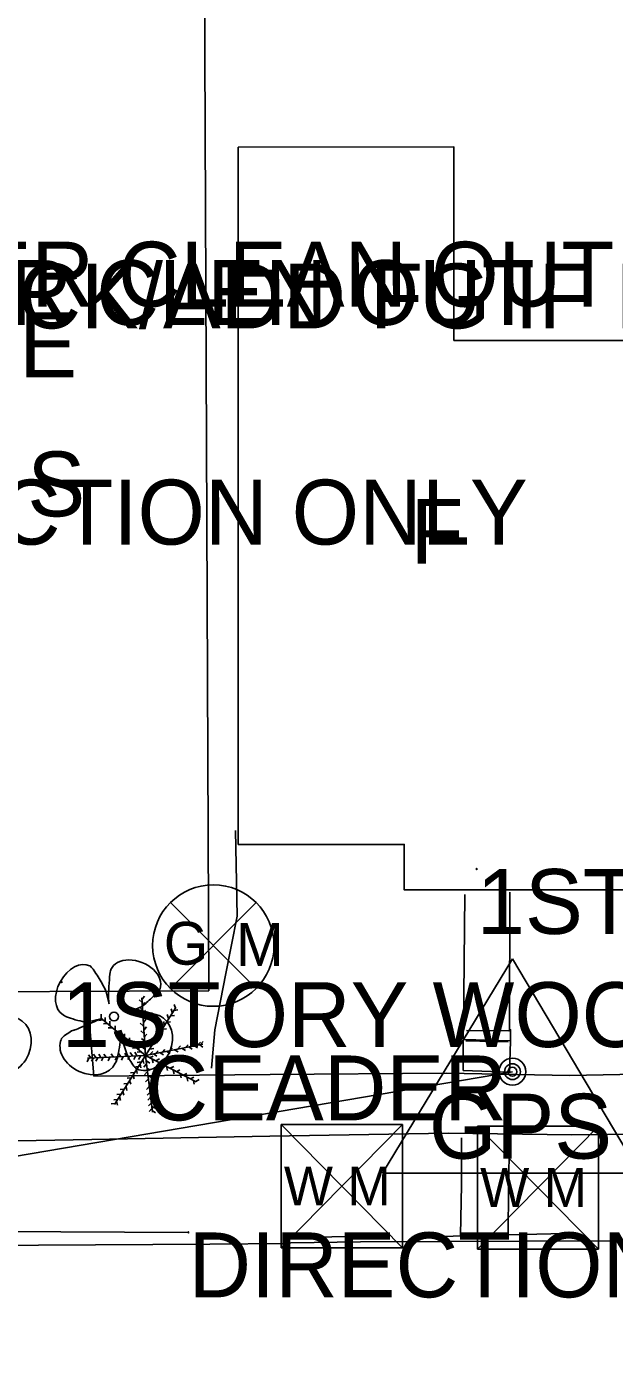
# Model space of a CAD drawing. Extents: x 1304270 to 1306561, y 1876019 to 1876752.
# Drawn here: x 1306274.6 to 1306320, y 1876424.3 to 1876526.4 of the extents above; entities that cross this region are included whole.
import ezdxf

# ---------------------------------------------------------------- set-up
doc = ezdxf.new("R2010")
doc.units = 0
for name, color, linetype in [('Default', 7, 'Continuous'), ('S_BUILDING', 7, 'Continuous'), ('S_BUILDING_ANNOT', 7, 'Continuous'), ('S_CURB', 7, 'Continuous'), ('S_DITCHLINE', 7, 'Continuous'), ('S_EDGE_CONCRETE', 7, 'Continuous'), ('S_EDGE_PAVEMENT', 7, 'Continuous'), ('S_GAS_UTILITIES', 7, 'Continuous'), ('S_MISC_STRUCTURES_ANNOT', 7, 'Continuous'), ('S_MSC_PT_SYM', 7, 'Continuous'), ('S_PRIMARY_CTL', 7, 'Continuous'), ('S_SANITARY_SEWER_ANNOT', 7, 'Continuous'), ('S_SIDEWALK', 7, 'Continuous'), ('S_STORM_SEWER', 7, 'Continuous'), ('S_STORM_SEWER_ANNOT', 7, 'Continuous'), ('S_STR_PT_SYM', 7, 'Continuous'), ('S_SURVEY_TEXT_ANNOT', 7, 'Continuous'), ('S_TREE', 7, 'Continuous'), ('S_TREE_ANNOT', 7, 'Continuous'), ('S_UTL_PT_SYM', 7, 'Continuous'), ('S_WATER_UTILITIES', 7, 'Continuous')]:
    doc.layers.add(name, color=color, linetype=linetype)

msp = doc.modelspace()

# ---------------------------------------------------------------- linework, layer by layer
at = {"layer": 'Default'}
msp.add_line((1305993.25, 1876391.55), (1306312.09, 1876445.88), dxfattribs=at)
at = {"layer": 'S_BUILDING'}
for points in [[(1306264.09, 1876452.02), (1306263.78, 1876530.37), (1306288.35, 1876530.47), (1306288.67, 1876452.12)], [(1306290.94, 1876517.15), (1306290.95, 1876463.4), (1306303.75, 1876463.4), (1306303.75, 1876459.89), (1306322.39, 1876459.89), (1306322.38, 1876502.24), (1306307.58, 1876502.24), (1306307.58, 1876517.16)]]:
    msp.add_lwpolyline(points, close=True, dxfattribs=at)
at = {"layer": 'S_CURB'}
for points in [[(1306295.32, 1876433.09), (1306299.61, 1876433.17)], [(1306306.43, 1876433.17), (1306316.12, 1876433.41)]]:
    msp.add_lwpolyline(points, dxfattribs=at)
at = {"layer": 'S_DITCHLINE'}
msp.add_lwpolyline([(1306290.74, 1876464.47), (1306290.85, 1876457.86), (1306289.99, 1876453.46), (1306289.14, 1876449.11), (1306288.88, 1876446.14)], dxfattribs=at)
at = {"layer": 'S_EDGE_CONCRETE'}
for points in [[(1306308.3, 1876445.97), (1306308.3, 1876448.25), (1306308.29, 1876448.38), (1306308.29, 1876449.07), (1306308.32, 1876449.22), (1306308.43, 1876459.54)], [(1306311.89, 1876459.71), (1306311.85, 1876449.16), (1306311.88, 1876449.02), (1306311.94, 1876449.12), (1306311.95, 1876448.96), (1306311.93, 1876448.26), (1306311.95, 1876448.23), (1306311.86, 1876445.84), (1306308.3, 1876445.97)], [(1306308.37, 1876448.37), (1306311.95, 1876448.26)], [(1306308.49, 1876448.27), (1306311.75, 1876448.17)], [(1306308.55, 1876449.06), (1306311.81, 1876449.03)]]:
    msp.add_lwpolyline(points, dxfattribs=at)
at = {"layer": 'S_EDGE_PAVEMENT'}
msp.add_lwpolyline([(1306113.12, 1876430.25), (1306126.16, 1876430.64), (1306148.96, 1876430.86), (1306171.76, 1876431.08), (1306196.43, 1876430.92), (1306201.22, 1876431.25), (1306201.59, 1876430.5), (1306204.64, 1876430.62), (1306209.26, 1876430.77), (1306212.62, 1876431.11), (1306218.85, 1876431.26), (1306235.37, 1876431.61), (1306256.72, 1876432.09), (1306262.37, 1876432.42), (1306275.55, 1876432.51), (1306288.74, 1876432.59), (1306294.65, 1876432.63), (1306294.99, 1876432.68), (1306300.36, 1876432.78), (1306312.86, 1876432.81), (1306325.37, 1876432.84), (1306326.28, 1876432.72), (1306334.35, 1876433.02), (1306341.35, 1876433.31)], dxfattribs=at)
at = {"layer": 'S_GAS_UTILITIES'}
for p, q in [((1306285.71, 1876452.29), (1306292.33, 1876458.91)), ((1306285.71, 1876458.91), (1306292.33, 1876452.29))]:
    msp.add_line(p, q, dxfattribs=at)
msp.add_circle((1306289.02, 1876455.6), 4.68, dxfattribs=at)
at = {"layer": 'S_MSC_PT_SYM'}
msp.add_lwpolyline([(1306277.32, 1876452.78), (1306277.32, 1876452.83), (1306277.32, 1876452.78), (1306277.28, 1876452.78), (1306277.32, 1876452.78), (1306277.32, 1876452.73), (1306277.32, 1876452.78), (1306277.38, 1876452.78)], dxfattribs=at)
at = {"layer": 'S_PRIMARY_CTL'}
for p, q in [((1306312.09, 1876454.58), (1306302.06, 1876438.07)), ((1306312.09, 1876454.58), (1306321.91, 1876438.07)), ((1306302.06, 1876438.07), (1306321.91, 1876438.07))]:
    msp.add_line(p, q, dxfattribs=at)
for radius in [1.04, 0.609, 0.344]:
    msp.add_circle((1306312.09, 1876445.88), radius, dxfattribs=at)
at = {"layer": 'S_SIDEWALK'}
for points in [[(1306279.53, 1876452.26), (1306279.47, 1876449.6), (1306279.8, 1876445.53)], [(1306279.8, 1876445.53), (1306293.4, 1876445.66), (1306307, 1876445.78)], [(1306307, 1876445.78), (1306316.52, 1876445.6), (1306328.09, 1876445.83), (1306340.2, 1876445.76), (1306355.77, 1876446.1)], [(1306258.08, 1876440.25), (1306262.7, 1876440.41), (1306268.2, 1876440.45), (1306279.65, 1876440.65), (1306293.39, 1876440.9), (1306307.14, 1876441.15), (1306316.67, 1876441.01), (1306327.71, 1876441.13), (1306341.95, 1876441.2), (1306356.19, 1876441.27)], [(1306308.16, 1876440.79), (1306308.15, 1876437.15), (1306308.08, 1876433.28)], [(1306311.77, 1876433.4), (1306311.79, 1876436.76), (1306311.87, 1876440.75)]]:
    msp.add_lwpolyline(points, dxfattribs=at)
at = {"layer": 'S_STORM_SEWER'}
msp.add_line((1306287.1, 1876433.49), (1306231.2, 1876433.73), dxfattribs=at)
at = {"layer": 'S_STR_PT_SYM'}
msp.add_lwpolyline([(1306309.34, 1876461.5), (1306309.34, 1876461.55), (1306309.34, 1876461.5), (1306309.29, 1876461.5), (1306309.34, 1876461.5), (1306309.34, 1876461.45), (1306309.34, 1876461.5), (1306309.39, 1876461.5)], dxfattribs=at)
at = {"layer": 'S_TREE'}
for p, q in [((1306280.99, 1876451.11), (1306280.75, 1876452.01)), ((1306283.53, 1876451.21), (1306283.31, 1876451.41)), ((1306283.79, 1876447.13), (1306283.52, 1876451.57)), ((1306283.53, 1876451.46), (1306283.72, 1876451.69)), ((1306283.56, 1876450.98), (1306283.74, 1876451.22)), ((1306280.36, 1876450.02), (1306280.36, 1876450.32)), ((1306282.94, 1876450.65), (1306283.32, 1876450.82)), ((1306283.56, 1876450.65), (1306283.34, 1876450.85)), ((1306283.59, 1876450.07), (1306283.37, 1876450.27)), ((1306283.59, 1876450.38), (1306283.78, 1876450.62)), ((1306283.79, 1876447.13), (1306286.13, 1876450.82)), ((1306285.56, 1876449.99), (1306285.47, 1876450.28)), ((1306285.75, 1876450.18), (1306286.04, 1876450.22)), ((1306285.86, 1876450.44), (1306285.77, 1876450.73)), ((1306285.99, 1876450.6), (1306286.29, 1876450.65)), ((1306286.1, 1876450.78), (1306286.01, 1876451.07)), ((1306280.34, 1876449.95), (1306279.37, 1876449.73)), ((1306280.5, 1876449.87), (1306280.2, 1876449.83)), ((1306283.79, 1876447.13), (1306280.32, 1876450.04)), ((1306280.85, 1876449.6), (1306280.55, 1876449.57)), ((1306280.68, 1876449.76), (1306280.68, 1876450.06)), ((1306281.21, 1876449.27), (1306280.91, 1876449.25)), ((1306281.03, 1876449.47), (1306281.03, 1876449.77)), ((1306281.44, 1876449.11), (1306281.44, 1876449.41)), ((1306283.62, 1876449.42), (1306283.39, 1876449.62)), ((1306283.63, 1876449.67), (1306283.82, 1876449.91)), ((1306283.69, 1876449.1), (1306283.88, 1876449.34)), ((1306284.89, 1876448.91), (1306284.8, 1876449.19)), ((1306285.1, 1876449.15), (1306285.4, 1876449.19)), ((1306285.26, 1876449.47), (1306285.17, 1876449.76)), ((1306285.42, 1876449.69), (1306285.72, 1876449.73)), ((1306281.67, 1876448.9), (1306281.37, 1876448.88)), ((1306282.03, 1876448.57), (1306281.73, 1876448.55)), ((1306281.86, 1876448.78), (1306281.86, 1876449.08)), ((1306281.88, 1876449.02), (1306281.96, 1876448.58)), ((1306282.37, 1876448.31), (1306282.07, 1876448.28)), ((1306282.18, 1876448.5), (1306282.18, 1876448.8)), ((1306282.55, 1876448.2), (1306282.55, 1876448.5)), ((1306282.91, 1876447.89), (1306282.91, 1876448.19)), ((1306283.66, 1876448.82), (1306283.43, 1876449.02)), ((1306283.7, 1876448.25), (1306283.47, 1876448.45)), ((1306283.7, 1876448.54), (1306283.89, 1876448.77)), ((1306284.23, 1876447.89), (1306284.14, 1876448.17)), ((1306284.59, 1876448.42), (1306284.5, 1876448.7)), ((1306284.75, 1876448.63), (1306285.05, 1876448.67)), ((1306287.81, 1876447.93), (1306288.02, 1876448.16)), ((1306288.04, 1876447.98), (1306288.24, 1876448.21)), ((1306283.79, 1876447.13), (1306279.33, 1876446.92)), ((1306279.57, 1876446.94), (1306279.4, 1876447.19)), ((1306279.95, 1876446.97), (1306279.79, 1876447.22)), ((1306280.35, 1876446.97), (1306280.19, 1876447.22)), ((1306280.75, 1876446.99), (1306280.59, 1876447.24)), ((1306281.32, 1876447.01), (1306281.15, 1876447.26)), ((1306283.79, 1876447.13), (1306281.4, 1876443.36)), ((1306281.88, 1876447.05), (1306281.71, 1876447.29)), ((1306282.35, 1876447.06), (1306282.19, 1876447.31)), ((1306282.71, 1876448.01), (1306282.41, 1876447.99)), ((1306282.79, 1876447.1), (1306282.62, 1876447.35)), ((1306283.08, 1876447.71), (1306282.78, 1876447.69)), ((1306283.13, 1876447.14), (1306282.96, 1876447.38)), ((1306283.44, 1876447.42), (1306283.14, 1876447.39)), ((1306283.27, 1876447.58), (1306283.27, 1876447.88)), ((1306283.71, 1876447.64), (1306283.48, 1876447.83)), ((1306283.73, 1876447.87), (1306283.92, 1876448.1)), ((1306283.79, 1876447.13), (1306288.21, 1876448)), ((1306283.79, 1876447.13), (1306287.7, 1876445.09)), ((1306283.79, 1876447.13), (1306284.32, 1876442.76)), ((1306284.13, 1876447.62), (1306284.43, 1876447.67)), ((1306284.16, 1876447.22), (1306284.36, 1876447.44)), ((1306284.4, 1876447.25), (1306284.66, 1876447.09)), ((1306284.42, 1876448.09), (1306284.71, 1876448.13)), ((1306284.56, 1876447.28), (1306284.76, 1876447.5)), ((1306284.92, 1876447.33), (1306285.17, 1876447.17)), ((1306285.09, 1876447.38), (1306285.29, 1876447.6)), ((1306285.44, 1876447.44), (1306285.69, 1876447.28)), ((1306285.66, 1876447.51), (1306285.86, 1876447.73)), ((1306286.04, 1876447.57), (1306286.3, 1876447.41)), ((1306286.29, 1876447.65), (1306286.49, 1876447.87)), ((1306286.62, 1876447.67), (1306286.88, 1876447.51)), ((1306286.88, 1876447.74), (1306287.09, 1876447.96)), ((1306287.13, 1876447.79), (1306287.39, 1876447.63)), ((1306287.37, 1876447.84), (1306287.57, 1876448.07)), ((1306287.56, 1876447.88), (1306287.81, 1876447.72)), ((1306287.97, 1876447.94), (1306288.22, 1876447.78)), ((1306279.42, 1876446.92), (1306279.28, 1876446.65)), ((1306279.77, 1876446.95), (1306279.63, 1876446.68)), ((1306280.11, 1876446.96), (1306279.97, 1876446.7)), ((1306280.53, 1876446.98), (1306280.39, 1876446.71)), ((1306281.04, 1876447), (1306280.9, 1876446.73)), ((1306281.6, 1876447.03), (1306281.46, 1876446.76)), ((1306282.08, 1876447.05), (1306281.95, 1876446.78)), ((1306282.55, 1876447.07), (1306282.42, 1876446.81)), ((1306283.01, 1876447.08), (1306282.88, 1876446.81)), ((1306283.22, 1876446.27), (1306282.92, 1876446.23)), ((1306283.46, 1876446.64), (1306283.16, 1876446.6)), ((1306283.4, 1876447.09), (1306283.26, 1876446.83)), ((1306283.37, 1876446.47), (1306283.44, 1876446.18)), ((1306283.58, 1876446.81), (1306283.65, 1876446.52)), ((1306283.85, 1876446.46), (1306283.65, 1876446.23)), ((1306283.86, 1876446.71), (1306284.12, 1876446.55)), ((1306283.9, 1876446.15), (1306284.16, 1876446)), ((1306284.11, 1876446.95), (1306284.38, 1876447.09)), ((1306284.3, 1876446.85), (1306284.37, 1876446.56)), ((1306284.59, 1876446.73), (1306284.86, 1876446.87)), ((1306284.88, 1876446.55), (1306284.95, 1876446.26)), ((1306285.15, 1876446.42), (1306285.41, 1876446.56)), ((1306285.41, 1876446.27), (1306285.48, 1876445.98)), ((1306285.7, 1876446.14), (1306285.97, 1876446.28)), ((1306282.69, 1876445.4), (1306282.39, 1876445.37)), ((1306282.57, 1876445.2), (1306282.65, 1876444.91)), ((1306282.94, 1876445.82), (1306282.64, 1876445.79)), ((1306282.83, 1876445.62), (1306282.91, 1876445.33)), ((1306283.09, 1876446.04), (1306283.16, 1876445.75)), ((1306283.91, 1876445.88), (1306283.72, 1876445.65)), ((1306284, 1876445.31), (1306283.8, 1876445.09)), ((1306283.99, 1876445.58), (1306284.24, 1876445.43)), ((1306285.93, 1876446), (1306286, 1876445.71)), ((1306286.19, 1876445.88), (1306286.45, 1876446.02)), ((1306286.47, 1876445.71), (1306286.54, 1876445.41)), ((1306286.72, 1876445.61), (1306286.99, 1876445.75)), ((1306286.99, 1876445.45), (1306287.06, 1876445.16)), ((1306287.27, 1876445.33), (1306287.53, 1876445.47)), ((1306287.48, 1876445.2), (1306287.55, 1876444.91)), ((1306287.66, 1876445.13), (1306287.93, 1876445.27)), ((1306281.89, 1876444.16), (1306281.59, 1876444.12)), ((1306282.13, 1876444.53), (1306281.83, 1876444.5)), ((1306282.04, 1876444.35), (1306282.12, 1876444.06)), ((1306282.42, 1876444.98), (1306282.13, 1876444.95)), ((1306282.29, 1876444.73), (1306282.36, 1876444.44)), ((1306284.07, 1876444.75), (1306283.87, 1876444.52)), ((1306284.13, 1876444.29), (1306283.93, 1876444.06)), ((1306284.05, 1876445.04), (1306284.31, 1876444.88)), ((1306284.12, 1876444.53), (1306284.38, 1876444.37)), ((1306284.15, 1876444.09), (1306284.41, 1876443.94)), ((1306281.44, 1876443.44), (1306281.14, 1876443.41)), ((1306281.64, 1876443.75), (1306281.34, 1876443.71)), ((1306281.56, 1876443.6), (1306281.64, 1876443.31)), ((1306281.79, 1876443.95), (1306281.86, 1876443.66)), ((1306284.17, 1876443.91), (1306283.97, 1876443.68)), ((1306284.23, 1876443.46), (1306284.03, 1876443.24)), ((1306284.27, 1876443.04), (1306284.08, 1876442.82)), ((1306284.2, 1876443.69), (1306284.45, 1876443.53)), ((1306284.26, 1876443.22), (1306284.52, 1876443.07)), ((1306284.3, 1876442.88), (1306284.56, 1876442.72))]:
    msp.add_line(p, q, dxfattribs=at)
msp.add_circle((1306281.36, 1876450.13), 0.341, dxfattribs=at)
for centre, major_axis, ratio, start_param, end_param in [((1306278.47, 1876452.15), (-1.03, -1.88), 0.662338, 3.141593, 6.283185), ((1306283.02, 1876453.02), (1.89, -0.74), 0.673998, 0, 3.141593), ((1306280.13, 1876453.02), (0.62, -1.01), 0.083512, 0, 3.141593), ((1306281.06, 1876452.44), (-0.07, -1.33), 0.068203, 3.141593, 6.283185), ((1306284.12, 1876451.55), (-0.798, -0.73), 0.092159, 0, 3.141593), ((1306278.41, 1876450), (0.964, -0.267), 0.113563, 3.141593, 6.283185), ((1306283.9, 1876450.42), (0.96, -0.23), 0.056001, 0, 3.141593), ((1306283.98, 1876448.15), (0.88, 2.05), 0.81717, 3.141593, 6.283185), ((1306273.09, 1876447.92), (0.88, 2.05), 0.81717, 3.141593, 6.283185), ((1306279.3, 1876449.51), (1.04, 0.44), 0.002756, 3.141593, 6.283185), ((1306279.38, 1876447.47), (2.07, -0.93), 0.760068, 3.141593, 6.283185), ((1306277.79, 1876448.74), (0.477, 0.328), 0.136309, 0, 3.141593), ((1306281.64, 1876447.85), (0.19, 1.31), 0.114148, 3.141593, 5.822668), ((1306282.21, 1876447.81), (0.254, -0.771), 0.051603, 3.141593, 6.283185), ((1306282.78, 1876446.57), (-0.321, 0.467), 0.094289, 0, 3.141593)]:
    msp.add_ellipse(centre, major_axis=major_axis, ratio=ratio, start_param=start_param, end_param=end_param, dxfattribs=at)
at = {"layer": 'S_UTL_PT_SYM'}
msp.add_lwpolyline([(1306287.1, 1876433.49), (1306287.1, 1876433.54), (1306287.1, 1876433.49), (1306287.05, 1876433.49), (1306287.1, 1876433.49), (1306287.1, 1876433.44), (1306287.1, 1876433.49), (1306287.15, 1876433.49)], dxfattribs=at)
at = {"layer": 'S_WATER_UTILITIES'}
for p, q in [((1306294.26, 1876441.8), (1306303.6, 1876441.8)), ((1306294.26, 1876441.8), (1306294.26, 1876432.31)), ((1306294.26, 1876441.8), (1306303.6, 1876432.31)), ((1306303.6, 1876441.8), (1306294.26, 1876432.31)), ((1306303.6, 1876441.8), (1306303.6, 1876432.31)), ((1306309.4, 1876441.69), (1306318.73, 1876441.69)), ((1306309.4, 1876441.69), (1306309.4, 1876432.19)), ((1306309.4, 1876441.69), (1306318.73, 1876432.19)), ((1306318.73, 1876441.69), (1306309.4, 1876432.19)), ((1306318.73, 1876441.69), (1306318.73, 1876432.19)), ((1306294.26, 1876432.31), (1306303.6, 1876432.31)), ((1306309.4, 1876432.19), (1306318.73, 1876432.19))]:
    msp.add_line(p, q, dxfattribs=at)

# ---------------------------------------------------------------- texts
at = {"layer": 'S_BUILDING_ANNOT'}
for s, p in [('S', (1306274.68, 1876488.68)), ('F', (1306304.24, 1876485.03)), ('1STRY WOOD BRICK ABANDON', (1306309.34, 1876456.5))]:
    msp.add_text(s, height=5, dxfattribs=at).set_placement(p)
at = {"layer": 'S_GAS_UTILITIES'}
for s, p in [('G', (1306285.2, 1876454.13)), ('M', (1306290.76, 1876454.03))]:
    msp.add_text(s, height=3.3, rotation=360, dxfattribs=at).set_placement(p)
at = {"layer": 'S_MISC_STRUCTURES_ANNOT'}
for s, p in [('SEWER CLEAN OUT', (1306255.3, 1876504.85)), ('SEWER CLEN OUT', (1306253.62, 1876503.43))]:
    msp.add_text(s, height=5, dxfattribs=at).set_placement(p)
at = {"layer": 'S_PRIMARY_CTL'}
msp.add_text('GPS', height=5, rotation=360, dxfattribs=at).set_placement((1306305.65, 1876439.18))
at = {"layer": 'S_SANITARY_SEWER_ANNOT'}
for s, p in [('OD BACK/ADD FG IF NEEDED', (1306253.18, 1876503.17)), ('SERVICE LINE', (1306232.45, 1876499.41))]:
    msp.add_text(s, height=5, dxfattribs=at).set_placement(p)
at = {"layer": 'S_STORM_SEWER_ANNOT'}
for s, p in [('30" RCP DIRECTION ONLY', (1306228.79, 1876486.51)), ('DIRECTION ONLY 30" RCP', (1306287.1, 1876428.49))]:
    msp.add_text(s, height=5, dxfattribs=at).set_placement(p)
at = {"layer": 'S_SURVEY_TEXT_ANNOT'}
msp.add_text('1STORY WOOD STUCCO BU ABANDONED BU', height=5, dxfattribs=at).set_placement((1306277.32, 1876447.78))
at = {"layer": 'S_TREE_ANNOT'}
msp.add_text('CEADER', height=5, dxfattribs=at).set_placement((1306283.79, 1876442.13))
at = {"layer": 'S_WATER_UTILITIES'}
for p in [(1306294.46, 1876435.57), (1306309.6, 1876435.45)]:
    msp.add_text('W M', height=3, rotation=360, dxfattribs=at).set_placement(p)

doc.saveas('drawing.dxf')
